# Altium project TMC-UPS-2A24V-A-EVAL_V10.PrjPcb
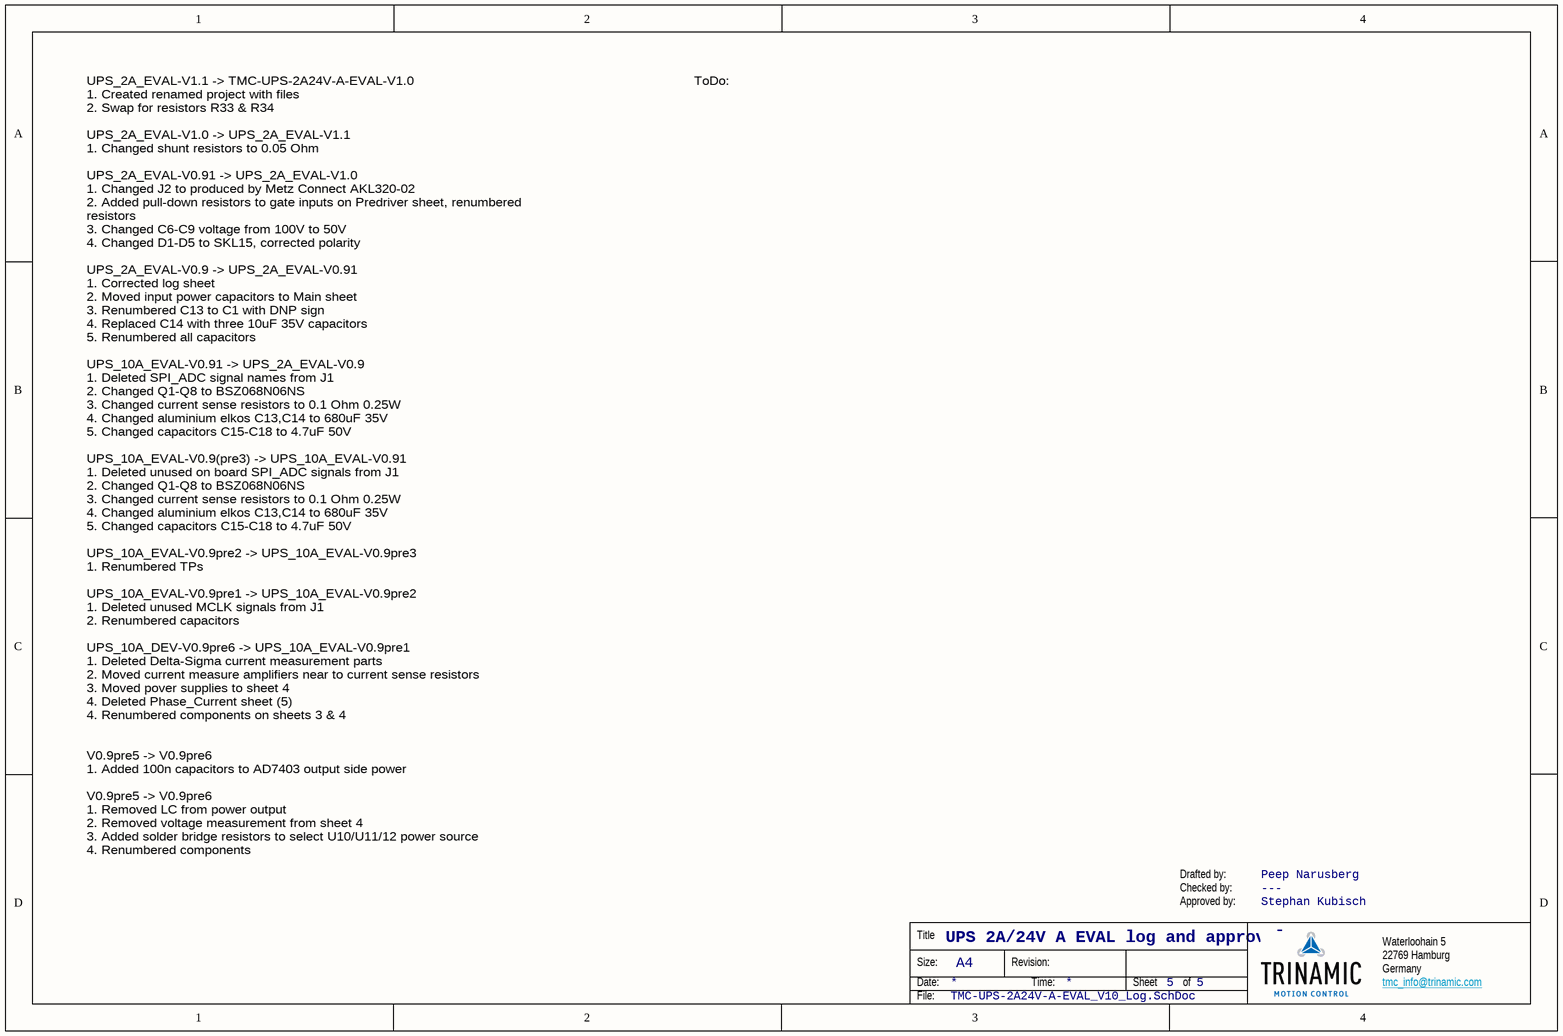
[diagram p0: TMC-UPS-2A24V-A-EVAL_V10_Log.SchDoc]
PName: UPS 2A/24V A EVAL; PRevision: V1.0
5 sheets, 128 parts. Net scope: flat (ports and power ports of the same name join across sheets).
Board file: TMC-UPS-2A24V-A-EVAL_V10.PcbDoc
Sheets:
  TMC-UPS-2A24V-A-EVAL_V10_Log.SchDoc
  TMC-UPS-2A24V-A-EVAL_V10_Main.SchDoc
  TMC-UPS-2A24V-A-EVAL_V10_MOSFETs.SchDoc
  TMC-UPS-2A24V-A-EVAL_V10_Power_Sense.SchDoc
  TMC-UPS-2A24V-A-EVAL_V10_Predriver.SchDoc

## Sheet TMC-UPS-2A24V-A-EVAL_V10_Log.SchDoc: log and approval
size A4; CompanyName: Hedgehog OÜ; Revision: V1.0; SheetNumber: 5; SheetTotal: 5; Author: Peep Narusberg; DrawnBy: Peep Narusberg; Engineer: Peep Narusberg; Organization: Hedgehog OÜ; Address1: Waterloohain 5; Address2: 22769 Hamburg; Address3: Germany; Address4: tmc_info@trinamic.com

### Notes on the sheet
- UPS_2A_EVAL-V1.1 -> TMC-UPS-2A24V-A-EVAL-V1.0
  1. Created renamed project with files
  2. Swap for resistors R33 & R34
  UPS_2A_EVAL-V1.0 -> UPS_2A_EVAL-V1.1
  1. Changed shunt resistors to 0.05 Ohm
  UPS_2A_EVAL-V0.91 -> UPS_2A_EVAL-V1.0
  1. Changed J2 to produced by Metz Connect AKL320-02
  2. Added pull-down resistors to gate inputs on Predriver sheet, renumbered resistors
  3. Changed C6-C9 voltage from 100V to 50V
  4. Changed D1-D5 to SKL15, corrected polarity
  UPS_2A_EVAL-V0.9 -> UPS_2A_EVAL-V0.91
  1. Corrected log sheet
  2. Moved input power capacitors to Main sheet
  3. Renumbered C13 to C1 with DNP sign
  4. Replaced C14 with three 10uF 35V capacitors
  5. Renumbered all capacitors
  UPS_10A_EVAL-V0.91 -> UPS_2A_EVAL-V0.9
  1. Deleted SPI_ADC signal names from J1
  2. Changed Q1-Q8 to BSZ068N06NS
  3. Changed current sense resistors to 0.1 Ohm 0.25W
  4. Changed aluminium elkos C13,C14 to 680uF 35V
  5. Changed capacitors C15-C18 to 4.7uF 50V
  UPS_10A_EVAL-V0.9(pre3) -> UPS_10A_EVAL-V0.91
  1. Deleted unused on board SPI_ADC signals from J1
  2. Changed Q1-Q8 to BSZ068N06NS
  3. Changed current sense resistors to 0.1 Ohm 0.25W
  4. Changed aluminium elkos C13,C14 to 680uF 35V
  5. Changed capacitors C15-C18 to 4.7uF 50V
  UPS_10A_EVAL-V0.9pre2 -> UPS_10A_EVAL-V0.9pre3
  1. Renumbered TPs
  UPS_10A_EVAL-V0.9pre1 -> UPS_10A_EVAL-V0.9pre2
  1. Deleted unused MCLK signals from J1
  2. Renumbered capacitors
  UPS_10A_DEV-V0.9pre6 -> UPS_10A_EVAL-V0.9pre1
  1. Deleted Delta-Sigma current measurement parts
  2. Moved current measure amplifiers near to current sense resistors
  3. Moved pover supplies to sheet 4
  4. Deleted Phase_Current sheet (5)
  4. Renumbered components on sheets 3 & 4
  V0.9pre5 -> V0.9pre6
  1. Added 100n capacitors to AD7403 output side power
  V0.9pre5 -> V0.9pre6
  1. Removed LC from power output
  2. Removed voltage measurement from sheet 4
  3. Added solder bridge resistors to select U10/U11/12 power source
  4. Renumbered components
  V0.9pre4 -> V0.9pre5
  1. Renamed net between J1 pin 9 and U8 pin 7 to MCLK_W
  2. Removed RC-s from power outputs
  3. Removed jumpers from current shunt circuit
  4. Disconnected J1 pin 5 from +5V
  5. Deleted SPI ADC part of circuit
  6. Corrected sheet 5 layout
  7. Corrected phase voltage net names
  8. Renumbered components
  V0.9pre3 -> V0.9pre4
  1. Added D5-D9 zeners
  2. Corrected net name HO_V_X2 for Q5
  3. Corrected SPI SDO signals (swap)
  V0.9pre2  -> V0.9pre3
  1. Added +3.3V source U16
  2. Added missing net names to JP3&4
  3. Checked current sense resistors calculation, changed footprint to 2010[5025 Metric]
  V0.9pre1 -> V0.9pre2
  1. Corrected net and port names
- ToDo:
- Drafted by:
- Checked by:
- Approved by:
- Peep Narusberg
- ---
- Stephan Kubisch

## Sheet TMC-UPS-2A24V-A-EVAL_V10_Main.SchDoc: Main & I/O
size A4; CompanyName: Hedgehog OÜ; Revision: 1; SheetNumber: 1; SheetTotal: 5; DrawnBy: Peep Narusberg; Engineer: Peep Narusberg; Organization: Hedgehog OÜ; Address1: Waterloohain 5; Address2: 22769 Hamburg; Address3: Germany; Address4: tmc_info@trinamic.com
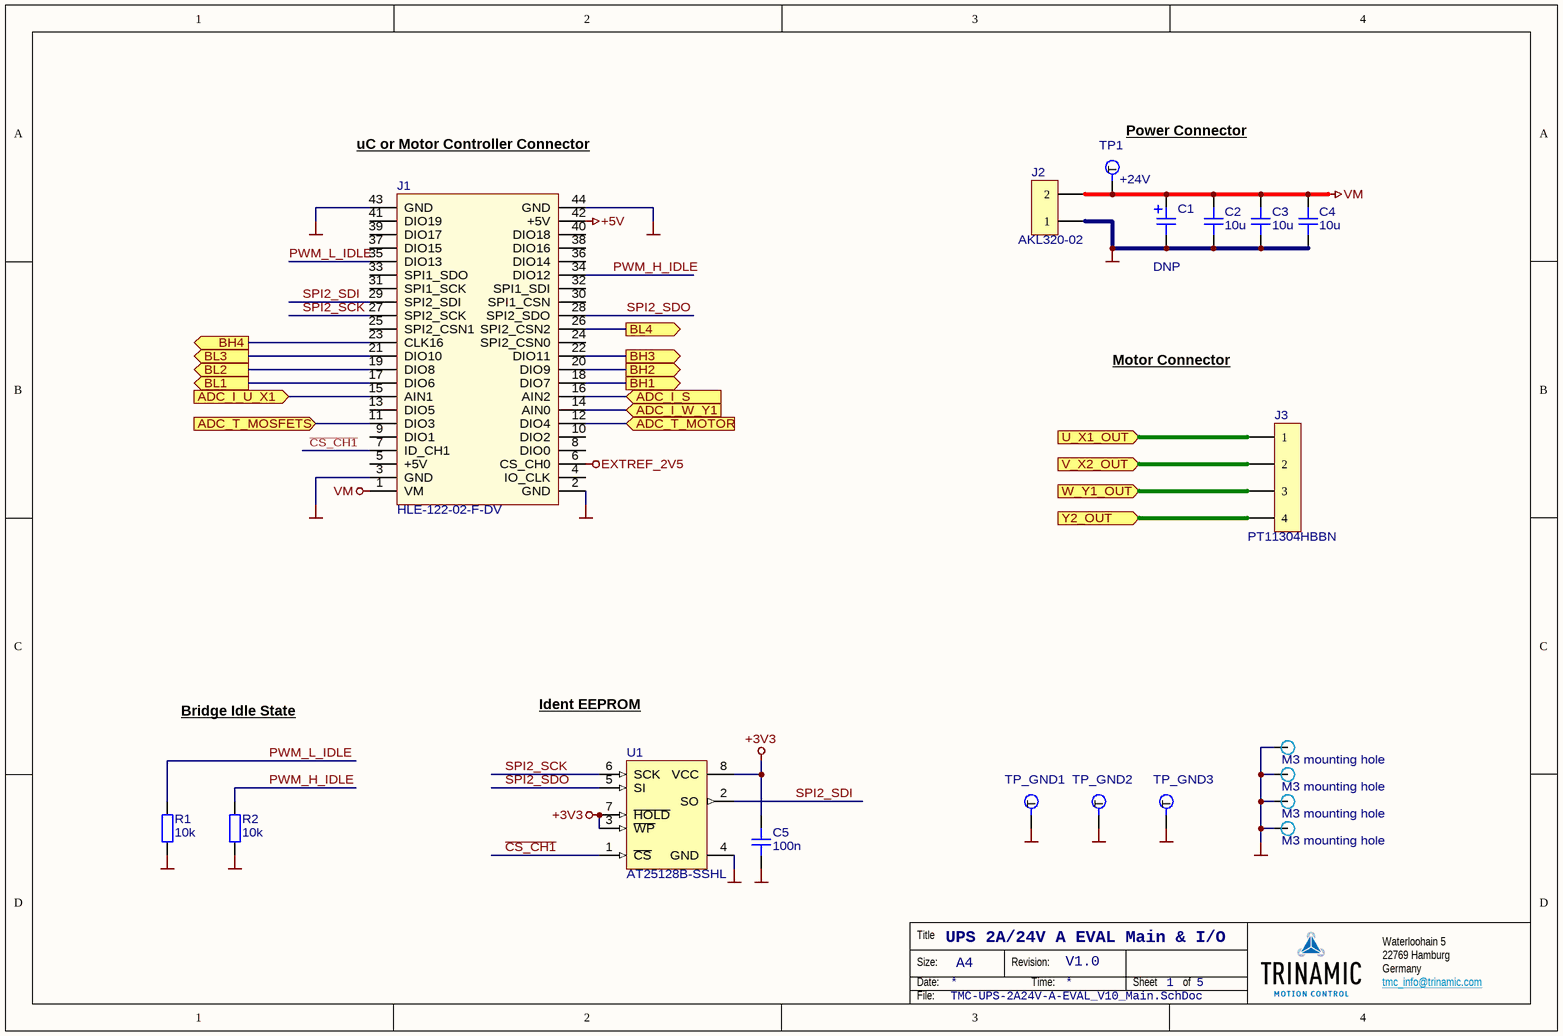
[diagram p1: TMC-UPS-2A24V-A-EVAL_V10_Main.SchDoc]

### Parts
C1  Part Number: DNP  [CAPAE12_5X20]  (hidden comment: CAPP2)
C2  value 10u  [CAPC3216N]  (hidden comment: CAPC)
C3  value 10u  [CAPC3216N]  (hidden comment: CAPC)
C4  value 10u  [CAPC3216N]  (hidden comment: CAPC)
C5  value 100n  [CAPC1608N]  (hidden comment: CAPC)
J1  PTC  [HLE-122-02-F-DV]  (value not drawn)
J2  HDR1x2A  [AKL320-02]  (value not drawn)
J3  HDR1x4A  [PT11304HBBN]  (value not drawn)
MP1  Part Number: M3 mounting hole  [MTG3,2_6,4-VIA]  (hidden comment: MTG)  (no BOM)
MP2  Part Number: M3 mounting hole  [MTG3,2_6,4-VIA]  (hidden comment: MTG)  (no BOM)
MP3  Part Number: M3 mounting hole  [MTG3,2_6,4-VIA]  (hidden comment: MTG)  (no BOM)
MP4  Part Number: M3 mounting hole  [MTG3,2_6,4-VIA]  (hidden comment: MTG)  (no BOM)
R1  value 10k  [RESC1608N]  (hidden comment: RESC)
R2  value 10k  [RESC1608N]  (hidden comment: RESC)
TP1  +24V  [TP100P254]  (no BOM)
TP_GND1  GND  [TP100P254-TH]  (value not drawn)  (no BOM)
TP_GND2  GND  [TP100P254-TH]  (value not drawn)  (no BOM)
TP_GND3  GND  [TP100P254]  (value not drawn)  (no BOM)
U1  Part Number: AT25128B-SSHL  [SOIC127P600X175-8N]

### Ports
ADC_I_S (in), ADC_I_U_X1 (in), ADC_I_W_Y1 (in), ADC_T_MOSFETS (in), ADC_T_MOTOR (in), BH1 (out), BH2 (out), BH3 (out), BH4 (out), BL1 (out), BL2 (out), BL3 (out), BL4 (out), U_X1_OUT (in), V_X2_OUT (in), W_Y1_OUT (in), Y2_OUT (in)

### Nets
+3V3: C5.2 U1.3(~{WP}) U1.7(~{HOLD}) U1.8(VCC)
+5V: J1.42(+5V)
EXTREF_2V5: J1.6(CS_CH0)
GND: C1.1 C2.1 C3.1 C4.1 C5.1 J1.2(GND) J1.3(GND) J1.43(GND) J1.44(GND) J2.1 MP1.1(GND) MP2.1(GND) MP3.1(GND) MP4.1(GND) R1.1 R2.1 TP_GND1.1(T) TP_GND2.1(T) TP_GND3.1(T) U1.4(GND)
VM: C1.2 C2.2 C3.2 C4.2 J1.1(VM) J2.2 TP1.1(T)
~{CS_CH1}: J1.7(ID_CH1) U1.1(~{CS})
PWM_H_IDLE: J1.34(DIO12) R2.2
PWM_L_IDLE: J1.35(DIO13) R1.2
SPI2_SCK: J1.27(SPI2_SCK) U1.6(SCK)
SPI2_SDI: J1.29(SPI2_SDI) U1.2(SO)
SPI2_SDO: J1.28(SPI2_SDO) U1.5(SI)
NetC7_2: J3.2 ; port V_X2_OUT
NetC9_2: J3.4 ; port Y2_OUT
NetC24_2: J1.16(AIN2) ; port ADC_I_S
NetC25_2: J1.11(DIO3) ; port ADC_T_MOSFETS
NetC26_2: J1.12(DIO4) ; port ADC_T_MOTOR
NetC28_2: J1.15(AIN1) ; port ADC_I_U_X1
NetC30_2: J1.14(AIN0) ; port ADC_I_W_Y1
NetJ1_17: J1.17(DIO6) ; port BL1
NetJ1_18: J1.18(DIO7) ; port BH1
NetJ1_19: J1.19(DIO8) ; port BL2
NetJ1_20: J1.20(DIO9) ; port BH2
NetJ1_21: J1.21(DIO10) ; port BL3
NetJ1_22: J1.22(DIO11) ; port BH3
NetJ1_23: J1.23(CLK16) ; port BH4
NetJ1_26: J1.26(SPI2_CSN2) ; port BL4
NetJ3_1: J3.1 ; port U_X1_OUT
NetJ3_3: J3.3 ; port W_Y1_OUT

Not connected (* = marked no-connect by the designer): J1 4(IO_CLK) 5(+5V) 8(DIO0) 9(DIO1) 10(DIO2) 13(DIO5) 24(SPI2_CSN0) 25(SPI2_CSN1) 30(SPI1_CSN) 31(SPI1_SCK) 32(SPI1_SDI) 33(SPI1_SDO) 36(DIO14) 37(DIO15) 38(DIO16) 39(DIO17) 40(DIO18) 41(DIO19)

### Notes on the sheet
- uC or Motor Controller Connector
- Power Connector
- Motor Connector
- Bridge Idle State
- Ident EEPROM

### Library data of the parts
C1 = 50527: Polarized capacitor, pin 1 neg; Id: 50527; Type: CAP
C2-C4 = 20034: Ceramic chip capacitor; Manufacturer: Any; Part Number: 10u, 35V, X5R, 1206 (3216 metric) chip capacitor; Id: 20034; Voltage: 35V
C5 = 20027: Ceramic chip capacitor; Manufacturer: Any; Part Number: 100n, 50V, X5R, 0603 (1608 metric) chip capacitor; Id: 20027; Voltage: 50V
J1 = 50289: Trinamic 44-pin connector; Manufacturer: Samtec; Id: 50289; Value: 44pin
J2 = 50537: 1X2 pin connector; Manufacturer: Metz Connect; Id: 50537; Value: 2 pin
J3 = 50511: 1X4 pin connector; Manufacturer: Metz Connect; Id: 50511; Value: 4 pin, 3.5mm
MP1-MP4 = 50193: Mounting hole; Id: 50193; Value: 3.2x6.4 VIA
R1 R2 = 10028: Chip Resistor; Manufacturer: Any; Part Number: 10k, 1%, 100mW, 0603 (1608 metric) chip resistor; Id: 10028; Power: 100mW; Tolerance: 1%
TP1 TP_GND3 = 50094: Round testpoint; Id: 50094; Value: c160 (P100 probe)
TP_GND1 TP_GND2 = 50149: Round testpoint; Id: 50149; Value: c160h100 (P100 TH)
U1 = 50499: SPI Serial Flash Memory; Manufacturer: Atmel; Id: 50499; Value: 128Kb

## Sheet TMC-UPS-2A24V-A-EVAL_V10_MOSFETs.SchDoc: MOSFETs
size A4; CompanyName: Hedgehog OÜ; Revision: 1; SheetNumber: 3; SheetTotal: 5; DrawnBy: Peep Narusberg; Engineer: Peep Narusberg; Organization: Hedgehog OÜ; Address1: Waterloohain 5; Address2: 22769 Hamburg; Address3: Germany; Address4: tmc_info@trinamic.com
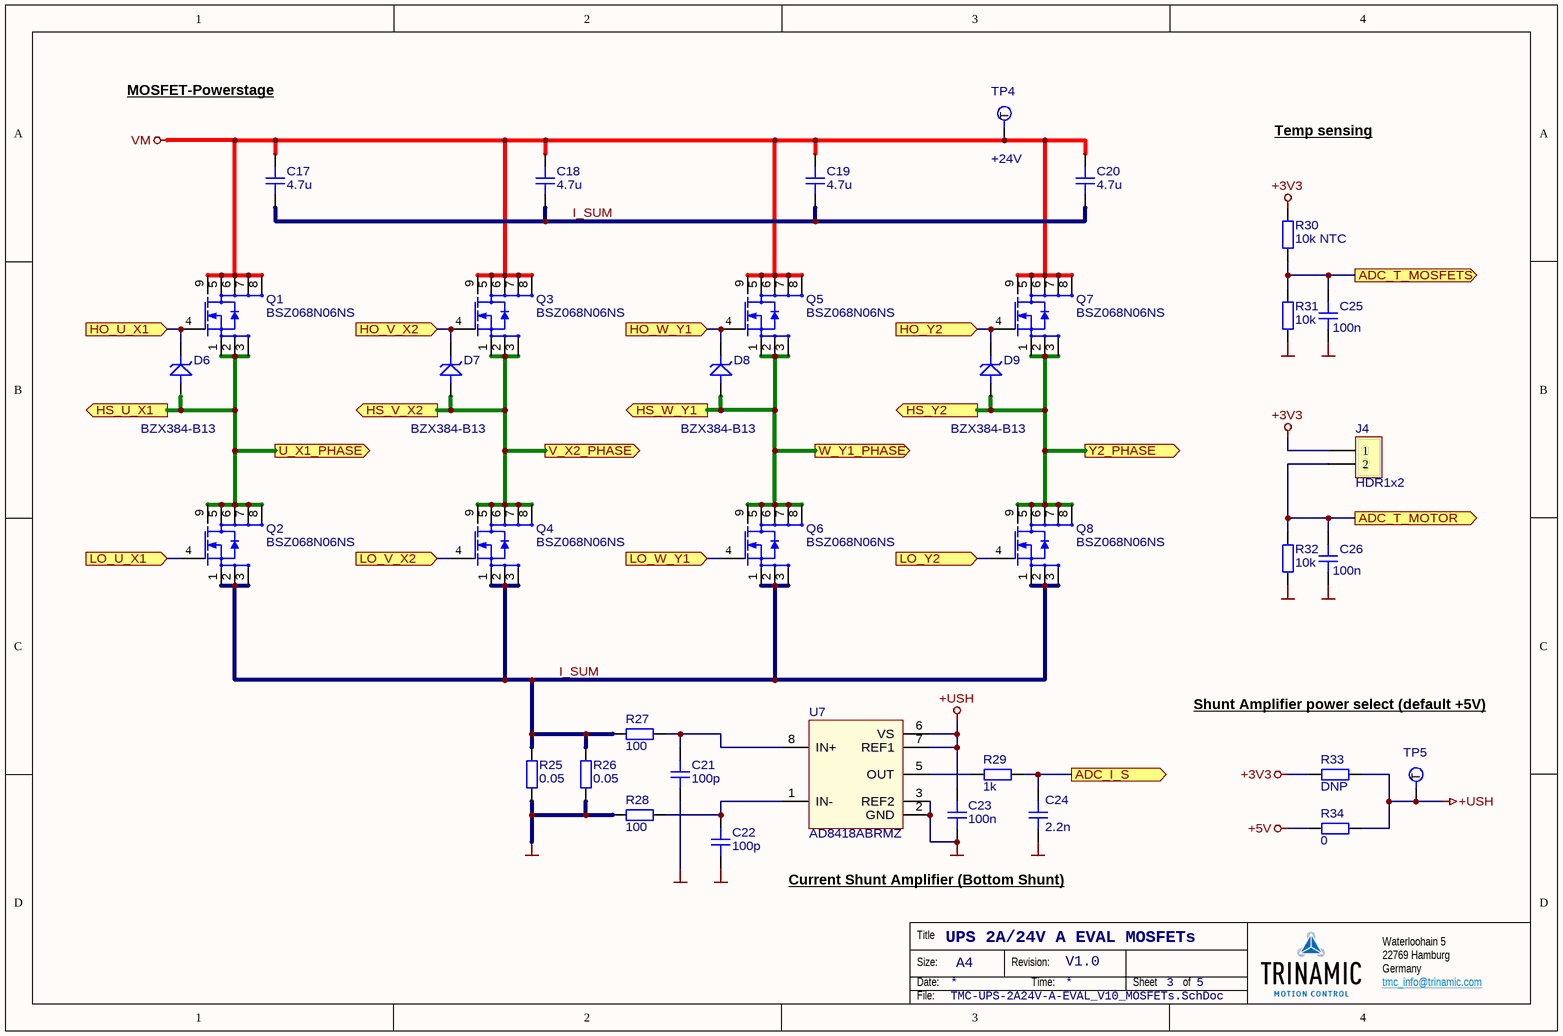
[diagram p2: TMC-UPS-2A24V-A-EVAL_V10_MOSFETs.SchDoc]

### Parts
C17  value 4.7u  [CAPC3216N]  (hidden comment: CAPC)
C18  value 4.7u  [CAPC3216N]  (hidden comment: CAPC)
C19  value 4.7u  [CAPC3216N]  (hidden comment: CAPC)
C20  value 4.7u  [CAPC3216N]  (hidden comment: CAPC)
C21  value 100p  [CAPC1608N]  (hidden comment: CAPC)
C22  value 100p  [CAPC1608N]  (hidden comment: CAPC)
C23  value 100n  [CAPC1608N]  (hidden comment: CAPC)
C24  value 2.2n  [CAPC1608N]
C25  value 100n  [CAPC1608N]  (hidden comment: CAPC)
C26  value 100n  [CAPC1608N]  (hidden comment: CAPC)
D6  Part Number: BZX384-B13  [SOD2512X100N]  (hidden comment: ZENER)
D7  Part Number: BZX384-B13  [SOD2512X100N]  (hidden comment: ZENER)
D8  Part Number: BZX384-B13  [SOD2512X100N]  (hidden comment: ZENER)
D9  Part Number: BZX384-B13  [SOD2512X100N]  (hidden comment: ZENER)
J4  HDR1x2  [HDRP1X2_2_54]
Q1  Part Number: BSZ068N06NS  [DFN65P300X90_HS-9N]  (hidden comment: MOSFET-ENH-N-8A)
Q2  Part Number: BSZ068N06NS  [DFN65P300X90_HS-9N]  (hidden comment: MOSFET-ENH-N-8A)
Q3  Part Number: BSZ068N06NS  [DFN65P300X90_HS-9N]  (hidden comment: MOSFET-ENH-N-8A)
Q4  Part Number: BSZ068N06NS  [DFN65P300X90_HS-9N]  (hidden comment: MOSFET-ENH-N-8A)
Q5  Part Number: BSZ068N06NS  [DFN65P300X90_HS-9N]  (hidden comment: MOSFET-ENH-N-8A)
Q6  Part Number: BSZ068N06NS  [DFN65P300X90_HS-9N]  (hidden comment: MOSFET-ENH-N-8A)
Q7  Part Number: BSZ068N06NS  [DFN65P300X90_HS-9N]  (hidden comment: MOSFET-ENH-N-8A)
Q8  Part Number: BSZ068N06NS  [DFN65P300X90_HS-9N]  (hidden comment: MOSFET-ENH-N-8A)
R25  value 0.05  [RESC2012N]  (hidden comment: RESC)
R26  value 0.05  [RESC2012N]  (hidden comment: RESC)
R27  value 100  [RESC1608N]  (hidden comment: RESC)
R28  value 100  [RESC1608N]  (hidden comment: RESC)
R29  value 1k  [RESC1608N]  (hidden comment: RESC)
R30  value 10k NTC  [RESC1608N]  (hidden comment: RESC)
R31  value 10k  [RESC1608N]  (hidden comment: RESC)
R32  value 10k  [RESC1608N]  (hidden comment: RESC)
R33  value DNP  [RESC1608N]  (hidden comment: RESC)
R34  value 0  [RESC1608N]  (hidden comment: RESC)
TP4  +24V  [TP100P254]  (no BOM)
TP5  +USH  [TP100P254]  (value not drawn)  (no BOM)
U7  Part Number: AD8418ABRMZ  [TSOP65P490X95-8N]  (hidden comment: *)

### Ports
ADC_I_S (out), ADC_T_MOSFETS (out), ADC_T_MOTOR (out), HO_U_X1 (in), HO_V_X2 (in), HO_W_Y1 (in), HO_Y2 (in), HS_U_X1 (out), HS_V_X2 (out), HS_W_Y1 (out), HS_Y2 (out), LO_U_X1 (in), LO_V_X2 (in), LO_W_Y1 (in), LO_Y2 (in), U_X1_PHASE (out), V_X2_PHASE (out), W_Y1_PHASE (out), Y2_PHASE (out)

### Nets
+3V3: J4.1 R30.2 R33.1
+5V: R34.1
+USH: C23.2 R33.2 R34.2 TP5.1(T) U7.6(VS) U7.7(REF1)
GND: C21.1 C22.1 C23.1 C24.1 C25.1 C26.1 R25.1 R26.1 R28.1 R31.1 R32.1 U7.2(GND) U7.3(REF2)
VM: C17.2 C18.2 C19.2 C20.2 Q1.5(D) Q1.6(D) Q1.7(D) Q1.8(D) Q1.9(D) Q3.5(D) Q3.6(D) Q3.7(D) Q3.8(D) Q3.9(D) Q5.5(D) Q5.6(D) Q5.7(D) Q5.8(D) Q5.9(D) Q7.5(D) Q7.6(D) Q7.7(D) Q7.8(D) Q7.9(D) TP4.1(T)
I_SUM: C17.1 C18.1 C19.1 C20.1 Q2.1(S) Q2.2(S) Q2.3(S) Q4.1(S) Q4.2(S) Q4.3(S) Q6.1(S) Q6.2(S) Q6.3(S) Q8.1(S) Q8.2(S) Q8.3(S) R25.2 R26.2 R27.1
NetC6_2: D6.2(A) Q1.1(S) Q1.2(S) Q1.3(S) Q2.5(D) Q2.6(D) Q2.7(D) Q2.8(D) Q2.9(D) ; port HS_U_X1, port U_X1_PHASE
NetC7_2: D7.2(A) Q3.1(S) Q3.2(S) Q3.3(S) Q4.5(D) Q4.6(D) Q4.7(D) Q4.8(D) Q4.9(D) ; port HS_V_X2, port V_X2_PHASE
NetC8_2: D8.2(A) Q5.1(S) Q5.2(S) Q5.3(S) Q6.5(D) Q6.6(D) Q6.7(D) Q6.8(D) Q6.9(D) ; port HS_W_Y1, port W_Y1_PHASE
NetC9_2: D9.2(A) Q7.1(S) Q7.2(S) Q7.3(S) Q8.5(D) Q8.6(D) Q8.7(D) Q8.8(D) Q8.9(D) ; port HS_Y2, port Y2_PHASE
NetC21_2: C21.2 R27.2 U7.8(IN+)
NetC22_2: C22.2 R28.2 U7.1(IN-)
NetC24_2: C24.2 R29.2 ; port ADC_I_S
NetC25_2: C25.2 R30.1 R31.2 ; port ADC_T_MOSFETS
NetC26_2: C26.2 J4.2 R32.2 ; port ADC_T_MOTOR
NetD6_1: D6.1(K) Q1.4(G) ; port HO_U_X1
NetD7_1: D7.1(K) Q3.4(G) ; port HO_V_X2
NetD8_1: D8.1(K) Q5.4(G) ; port HO_W_Y1
NetD9_1: D9.1(K) Q7.4(G) ; port HO_Y2
NetQ2_4: Q2.4(G) ; port LO_U_X1
NetQ4_4: Q4.4(G) ; port LO_V_X2
NetQ6_4: Q6.4(G) ; port LO_W_Y1
NetQ8_4: Q8.4(G) ; port LO_Y2
NetR29_1: R29.1 U7.5(OUT)

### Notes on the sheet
- MOSFET-Powerstage
- Temp sensing
- Shunt Amplifier power select (default +5V)
- Current Shunt Amplifier (Bottom Shunt)

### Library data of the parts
C17-C20 = 20078: Ceramic chip capacitor; Manufacturer: Any; Part Number: 4.7u, 50V, X5R, 1206 (3216 metric) chip capacitor; Id: 20078; Voltage: 50V
C21 C22 = 20083: Ceramic chip capacitor; Manufacturer: Any; Part Number: 100p, 100V, C0G/NP0, 0603 (1608 metric) chip capacitor; Id: 20083; Voltage: 100V
C23 C25 C26 = 20027: as C5 on sheet TMC-UPS-2A24V-A-EVAL_V10_Main
C24 = 20056: Ceramic chip capacitor; Manufacturer: Any; Part Number: 2.2n, 50V, C0G/NP0, 0603 (1608 metric) chip capacitor; Id: 20056; Voltage: 50V
D6-D9 = 50513: Zener, pin1 cathode; Manufacturer: Nexperia; Id: 50513; Type: ZEN; Value: 13V, 0.3W
J4 = 50023: 1X2 pin connector; Part Number: 1x2 2.54mm pin header; Manufacturer: Any; Id: 50023; Value: 2 pin
Q1-Q8 = 50524: N-ch Enh-MOSFET; 5,6,7,8D 4G 1,2.3S; Manufacturer: Infineon; Id: 50524; Type: MOSFETN; Value: 60V 40A
R25 R26 = 10172: Chip Resistor; Manufacturer: Any; Part Number: 0.05, 1%, 250mW, 0805 (2012 metric) chip resistor; Id: 10172; Power: 250mW; Tolerance: 1%
R27 R28 = 10016: Chip Resistor; Manufacturer: Any; Part Number: 100, 1%, 100mW, 0603 (1608 metric) chip resistor; Id: 10016; Power: 100mW; Tolerance: 1%
R29 = 10049: Chip Resistor; Manufacturer: Any; Part Number: 1k, 1%, 100mW, 0603 (1608 metric) chip resistor; Id: 10049; Power: 100mW; Tolerance: 1%
R30 = 40000: Chip Resistor; Manufacturer: Epcos; Part Number: B57330V2103J260; Id: 40000; Power: 180mW; Tolerance: 5%
R31 R32 = 10028: as R1 on sheet TMC-UPS-2A24V-A-EVAL_V10_Main
R33 = 40007: Chip Resistor; Id: 40007
R34 = 10054: Chip Resistor; Manufacturer: Any; Part Number: 0, -, -, 0603 (1608 metric) chip resistor; Id: 10054
TP4 TP5 = 50094: as TP1 on sheet TMC-UPS-2A24V-A-EVAL_V10_Main
U7 = 50496: Bidirectional, Zero Drift, Current Sense Amplifier; Manufacturer: Analog Devices; Id: 50496; Value: CMVR=70V

## Sheet TMC-UPS-2A24V-A-EVAL_V10_Power_Sense.SchDoc: Power Sense
size A4; CompanyName: Hedgehog OÜ; Revision: 1; SheetNumber: 4; SheetTotal: 5; DrawnBy: Peep Narusberg; Engineer: Peep Narusberg; Organization: Hedgehog OÜ; Address1: Waterloohain 5; Address2: 22769 Hamburg; Address3: Germany; Address4: tmc_info@trinamic.com
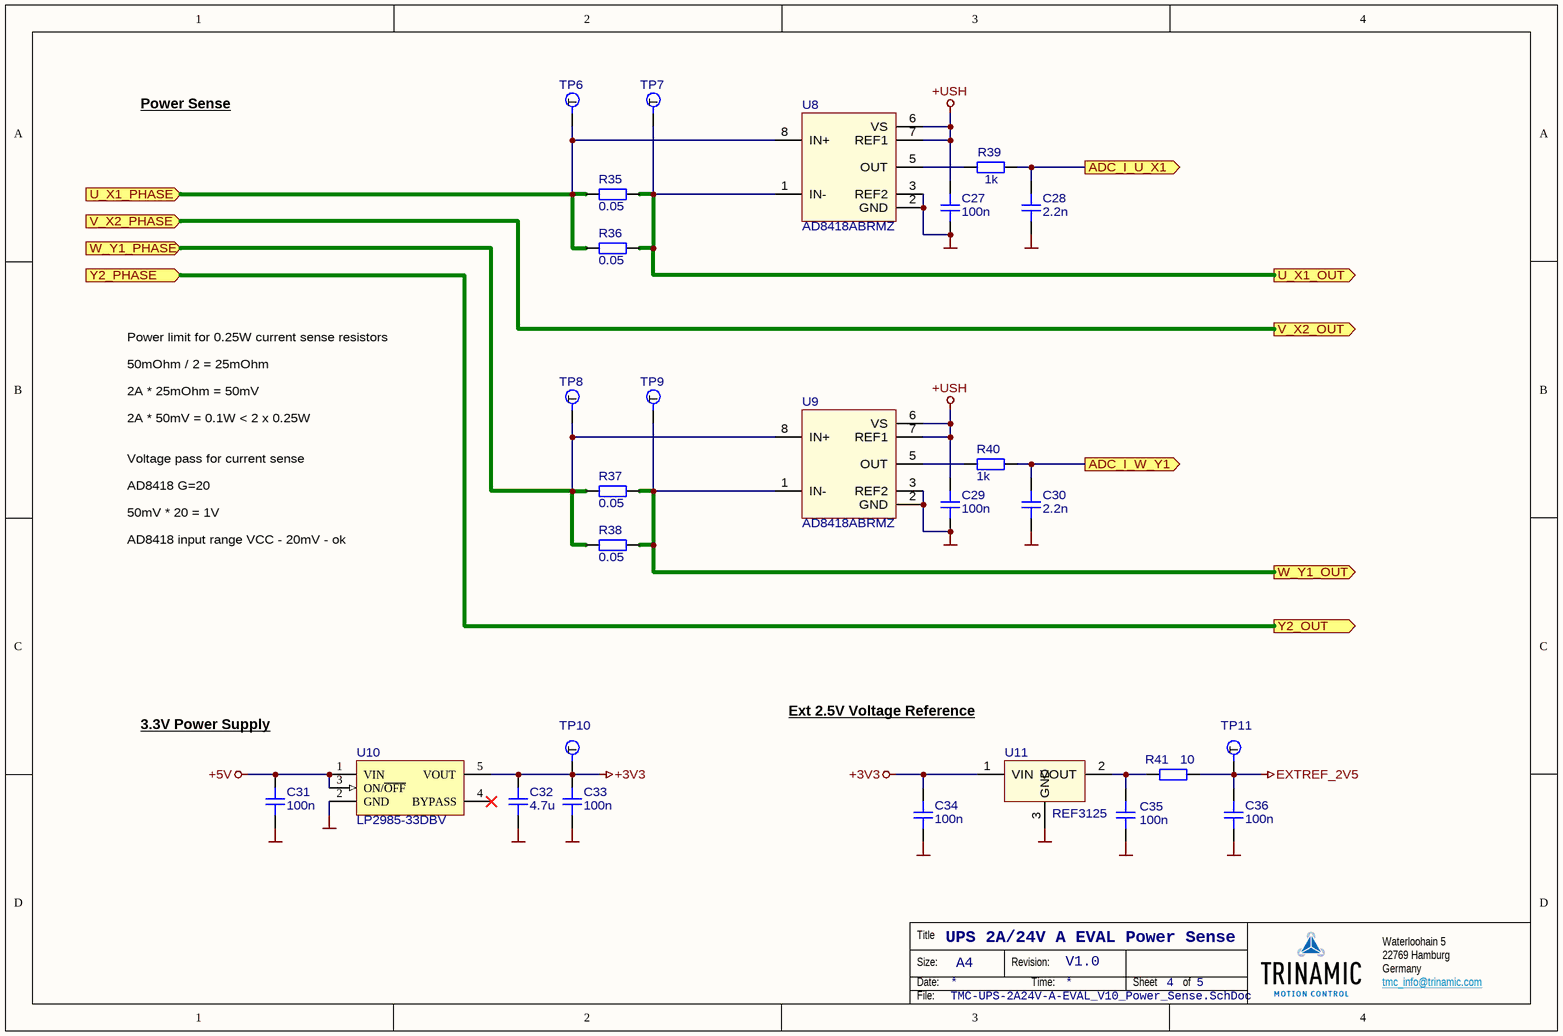
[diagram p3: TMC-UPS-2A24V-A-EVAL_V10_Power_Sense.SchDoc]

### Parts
C27  value 100n  [CAPC1608N]  (hidden comment: CAPC)
C28  value 2.2n  [CAPC1608N]
C29  value 100n  [CAPC1608N]  (hidden comment: CAPC)
C30  value 2.2n  [CAPC1608N]
C31  value 100n  [CAPC1608N]  (hidden comment: CAPC)
C32  value 4.7u  [CAPC1608N]  (hidden comment: CAPC)
C33  value 100n  [CAPC1608N]  (hidden comment: CAPC)
C34  value 100n  [CAPC1608N]  (hidden comment: CAPC)
C35  value 100n  [CAPC1608N]  (hidden comment: CAPC)
C36  value 100n  [CAPC1608N]  (hidden comment: CAPC)
R35  value 0.05  [RESC2012N]  (hidden comment: RESC)
R36  value 0.05  [RESC2012N]  (hidden comment: RESC)
R37  value 0.05  [RESC2012N]  (hidden comment: RESC)
R38  value 0.05  [RESC2012N]  (hidden comment: RESC)
R39  value 1k  [RESC1608N]  (hidden comment: RESC)
R40  value 1k  [RESC1608N]  (hidden comment: RESC)
R41  value 10  [RESC1608N]  (hidden comment: RESC)
TP6  SENSE_X+  [TP100P254]  (value not drawn)  (no BOM)
TP7  SENSE_X-  [TP100P254]  (value not drawn)  (no BOM)
TP8  SENSE_Y+  [TP100P254]  (value not drawn)  (no BOM)
TP9  SENSE_Y-  [TP100P254]  (value not drawn)  (no BOM)
TP10  +3V3  [TP100P254]  (value not drawn)  (no BOM)
TP11  EXTREF 2V5  [TP100P254]  (value not drawn)  (no BOM)
U8  Part Number: AD8418ABRMZ  [TSOP65P490X95-8N]  (hidden comment: *)
U9  Part Number: AD8418ABRMZ  [TSOP65P490X95-8N]  (hidden comment: *)
U10  Part Number: LP2985-33DBV  [SOT95P270X145-5N]
U11  Part Number: REF3125  [SOT95P280X130-3N]  (hidden comment: *)

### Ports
ADC_I_U_X1 (out), ADC_I_W_Y1 (out), U_X1_OUT (out), U_X1_PHASE (in), V_X2_OUT (out), V_X2_PHASE (in), W_Y1_OUT (out), W_Y1_PHASE (in), Y2_OUT (out), Y2_PHASE (in)

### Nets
+3V3: C32.2 C33.2 C34.2 TP10.1(T) U10.5(VOUT) U11.1(VIN)
+5V: C31.2 U10.1(VIN) U10.3(ON/~{OFF})
+USH: C27.1 C29.2 U8.6(VS) U8.7(REF1) U9.6(VS) U9.7(REF1)
EXTREF_2V5: C36.2 R41.2 TP11.1(T)
GND: C27.2 C28.1 C29.1 C30.1 C31.1 C32.1 C33.1 C34.1 C35.1 C36.1 U8.2(GND) U8.3(REF2) U9.2(GND) U9.3(REF2) U10.2(GND) U11.3(GND)
NetC6_2: R35.1 R36.1 TP6.1(T) U8.8(IN+) ; port U_X1_PHASE
NetC7_2: port V_X2_PHASE, port V_X2_OUT
NetC8_2: R37.1 R38.1 TP8.1(T) U9.8(IN+) ; port W_Y1_PHASE
NetC9_2: port Y2_PHASE, port Y2_OUT
NetC28_2: C28.2 R39.2 ; port ADC_I_U_X1
NetC30_2: C30.2 R40.2 ; port ADC_I_W_Y1
NetC35_2: C35.2 R41.1 U11.2(VOUT)
NetJ3_1: R35.2 R36.2 TP7.1(T) U8.1(IN-) ; port U_X1_OUT
NetJ3_3: R37.2 R38.2 TP9.1(T) U9.1(IN-) ; port W_Y1_OUT
NetR39_1: R39.1 U8.5(OUT)
NetR40_1: R40.1 U9.5(OUT)

Not connected (* = marked no-connect by the designer): U10 4(BYPASS)*

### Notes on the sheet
- Power Sense
- Power limit for 0.25W current sense resistors
  50mOhm / 2 = 25mOhm
  2A * 25mOhm = 50mV
  2A * 50mV = 0.1W < 2 x 0.25W
  Voltage pass for current sense
  AD8418 G=20
  50mV * 20 = 1V
  AD8418 input range VCC - 20mV - ok
- Ext 2.5V Voltage Reference
- 3.3V Power Supply

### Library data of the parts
C27 C29 C31 C33-C36 = 20027: as C5 on sheet TMC-UPS-2A24V-A-EVAL_V10_Main
C28 C30 = 20056: as C24 on sheet TMC-UPS-2A24V-A-EVAL_V10_MOSFETs
C32 = 20084: Ceramic chip capacitor; Manufacturer: Any; Part Number: 4.7u, 10V, X5R, 0603 (1608 metric) chip capacitor; Id: 20084; Voltage: 10V
R35-R38 = 10172: as R25 on sheet TMC-UPS-2A24V-A-EVAL_V10_MOSFETs
R39 R40 = 10049: as R29 on sheet TMC-UPS-2A24V-A-EVAL_V10_MOSFETs
R41 = 10002: Chip Resistor; Manufacturer: Any; Part Number: 10, 1%, 100mW, 0603 (1608 metric) chip resistor; Id: 10002; Power: 100mW; Tolerance: 1%
TP6-TP11 = 50094: as TP1 on sheet TMC-UPS-2A24V-A-EVAL_V10_Main
U8 U9 = 50496: as U7 on sheet TMC-UPS-2A24V-A-EVAL_V10_MOSFETs
U10 = 50426: 150-mA Low-noise LDO; Manufacturer: Texas Instruments; Id: 50426; Value: 150mA 3.3V
U11 = 50316: Series voltage reference; Manufacturer: Texas Instruments; Id: 50316; Value: 2.5V

## Sheet TMC-UPS-2A24V-A-EVAL_V10_Predriver.SchDoc: Predrivers
size A4; CompanyName: Hedgehog OÜ; Revision: 1; SheetNumber: 2; SheetTotal: 6; DrawnBy: Peep Narusberg; Engineer: Peep Narusberg; Organization: Hedgehog OÜ; Address1: Waterloohain 5; Address2: 22769 Hamburg; Address3: Germany; Address4: tmc_info@trinamic.com
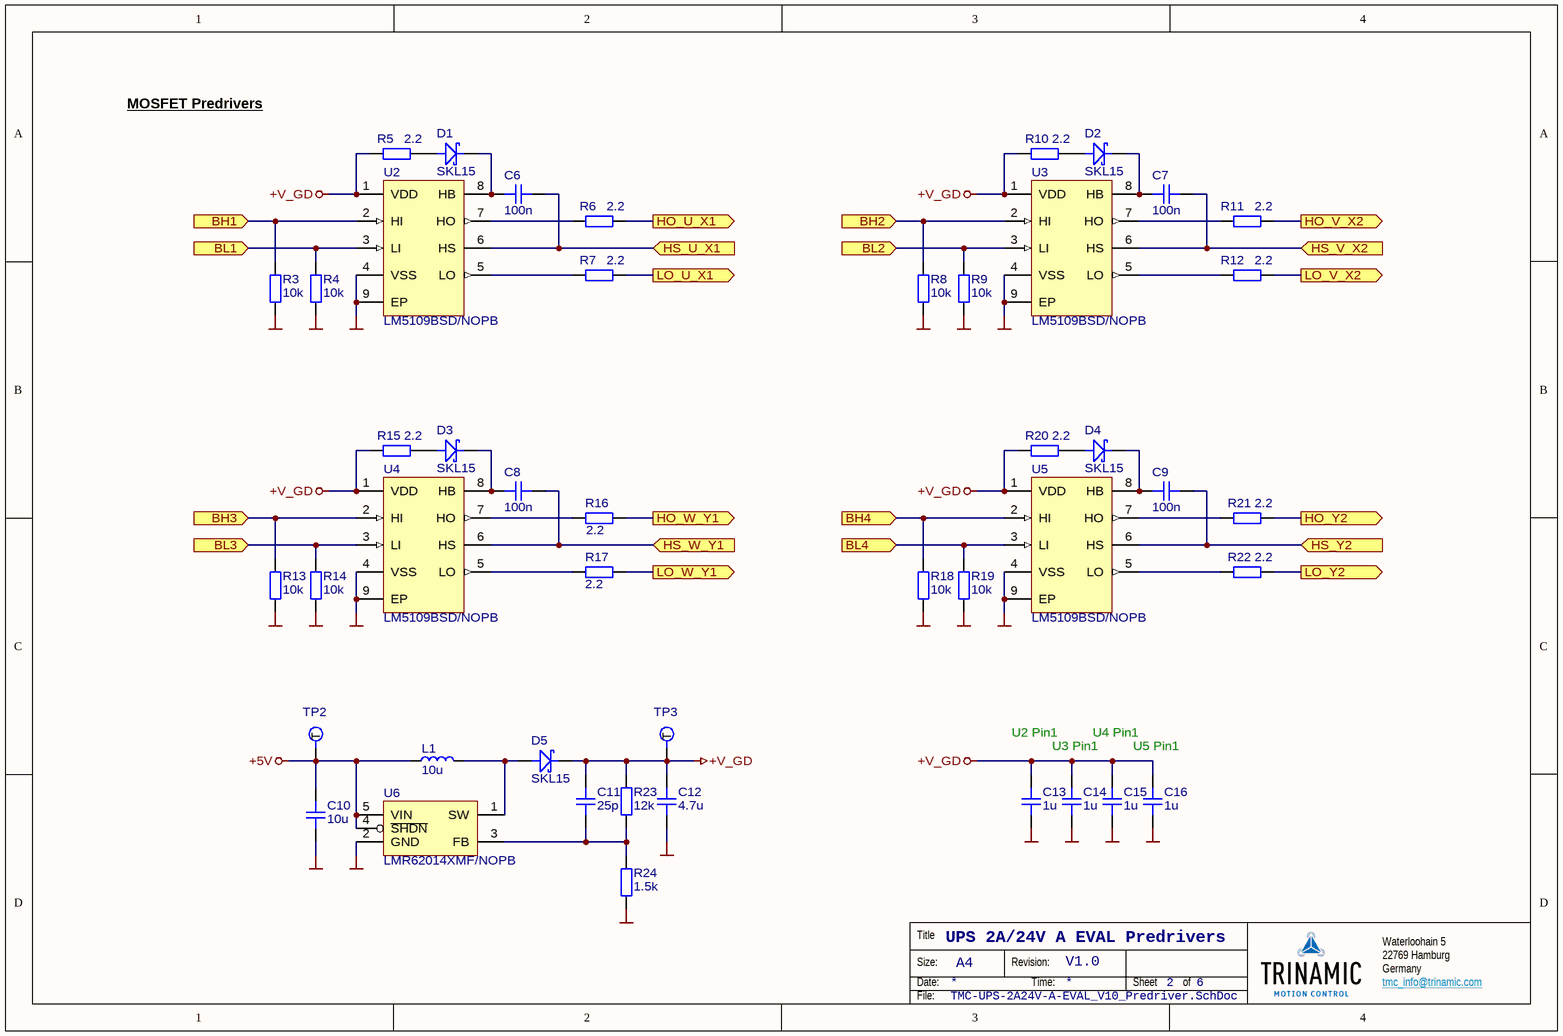
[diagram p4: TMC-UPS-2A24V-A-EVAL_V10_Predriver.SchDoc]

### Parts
C6  value 100n  [CAPC1608N]  (hidden comment: CAPC)
C7  value 100n  [CAPC1608N]  (hidden comment: CAPC)
C8  value 100n  [CAPC1608N]  (hidden comment: CAPC)
C9  value 100n  [CAPC1608N]  (hidden comment: CAPC)
C10  value 10u  [CAPC1608N]  (hidden comment: CAPC)
C11  value 25p  [CAPC1608N]  (hidden comment: CAPC)
C12  value 4.7u  [CAPC1608N]  (hidden comment: CAPC)
C13  value 1u  [CAPC1608N]  (hidden comment: CAPC)
C14  value 1u  [CAPC1608N]  (hidden comment: CAPC)
C15  value 1u  [CAPC1608N]  (hidden comment: CAPC)
C16  value 1u  [CAPC1608N]  (hidden comment: CAPC)
D1  Part Number: SKL15  [SODFL370X140-2N]  (hidden comment: DIO-SCHOTTKY)
D2  Part Number: SKL15  [SODFL370X140-2N]  (hidden comment: DIO-SCHOTTKY)
D3  Part Number: SKL15  [SODFL370X140-2N]  (hidden comment: DIO-SCHOTTKY)
D4  Part Number: SKL15  [SODFL370X140-2N]  (hidden comment: DIO-SCHOTTKY)
D5  Part Number: SKL15  [SODFL370X140-2N]  (hidden comment: DIO-SCHOTTKY)
L1  value 10u  [744031100]  (hidden comment: INDM)
R3  value 10k  [RESC1608N]  (hidden comment: RESC)
R4  value 10k  [RESC1608N]  (hidden comment: RESC)
R5  value 2.2  [RESC1608N]
R6  value 2.2  [RESC1608N]
R7  value 2.2  [RESC1608N]
R8  value 10k  [RESC1608N]  (hidden comment: RESC)
R9  value 10k  [RESC1608N]  (hidden comment: RESC)
R10  value 2.2  [RESC1608N]
R11  value 2.2  [RESC1608N]
R12  value 2.2  [RESC1608N]
R13  value 10k  [RESC1608N]  (hidden comment: RESC)
R14  value 10k  [RESC1608N]  (hidden comment: RESC)
R15  value 2.2  [RESC1608N]
R16  value 2.2  [RESC1608N]
R17  value 2.2  [RESC1608N]
R18  value 10k  [RESC1608N]  (hidden comment: RESC)
R19  value 10k  [RESC1608N]  (hidden comment: RESC)
R20  value 2.2  [RESC1608N]
R21  value 2.2  [RESC1608N]
R22  value 2.2  [RESC1608N]
R23  value 12k  [RESC1608N]  (hidden comment: RESC)
R24  value 1.5k  [RESC1608N]  (hidden comment: RESC)
TP2  +5V  [TP100P254]  (value not drawn)  (no BOM)
TP3  +V_GD  [TP100P254]  (value not drawn)  (no BOM)
U2  Part Number: LM5109BSD/NOPB  [PSON80P400X80_HS-9N]
U3  Part Number: LM5109BSD/NOPB  [PSON80P400X80_HS-9N]
U4  Part Number: LM5109BSD/NOPB  [PSON80P400X80_HS-9N]
U5  Part Number: LM5109BSD/NOPB  [PSON80P400X80_HS-9N]
U6  Part Number: LMR62014XMF/NOPB  [SOT95P280X145-5N]  (hidden comment: LMR62014)

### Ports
BH1 (in), BH2 (in), BH3 (in), BH4 (in), BL1 (in), BL2 (in), BL3 (in), BL4 (in), HO_U_X1 (out), HO_V_X2 (out), HO_W_Y1 (out), HO_Y2 (out), HS_U_X1 (in), HS_V_X2 (in), HS_W_Y1 (in), HS_Y2 (in), LO_U_X1 (out), LO_V_X2 (out), LO_W_Y1 (out), LO_Y2 (out)

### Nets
+5V: C10.2 L1.1 TP2.1(T) U6.4(~{SHDN}) U6.5(VIN)
+V_GD: C11.2 C12.2 C13.2 C14.2 C15.2 C16.2 D5.1 R5.1 R10.1 R15.1 R20.1 R23.2 TP3.1(T) U2.1(VDD) U3.1(VDD) U4.1(VDD) U5.1(VDD)
GND: C10.1 C12.1 C13.1 C14.1 C15.1 C16.1 R3.1 R4.1 R8.1 R9.1 R13.1 R14.1 R18.1 R19.1 R24.1 U2.4(VSS) U2.9(EP) U3.4(VSS) U3.9(EP) U4.4(VSS) U4.9(EP) U5.4(VSS) U5.9(EP) U6.2(GND)
NetC6_1: C6.1 D1.1 U2.8(HB)
NetC6_2: C6.2 U2.6(HS) ; port HS_U_X1
NetC7_1: C7.1 D2.1 U3.8(HB)
NetC7_2: C7.2 U3.6(HS) ; port HS_V_X2
NetC8_1: C8.1 D3.1 U4.8(HB)
NetC8_2: C8.2 U4.6(HS) ; port HS_W_Y1
NetC9_1: C9.1 D4.1 U5.8(HB)
NetC9_2: C9.2 U5.6(HS) ; port HS_Y2
NetC11_1: C11.1 R23.1 R24.2 U6.3(FB)
NetD1_2: D1.2 R5.2
NetD2_2: D2.2 R10.2
NetD3_2: D3.2 R15.2
NetD4_2: D4.2 R20.2
NetD5_2: D5.2 L1.2 U6.1(SW)
NetD6_1: R6.2 ; port HO_U_X1
NetD7_1: R11.2 ; port HO_V_X2
NetD8_1: R16.2 ; port HO_W_Y1
NetD9_1: R21.2 ; port HO_Y2
NetJ1_17: R4.2 U2.3(LI) ; port BL1
NetJ1_18: R3.2 U2.2(HI) ; port BH1
NetJ1_19: R9.2 U3.3(LI) ; port BL2
NetJ1_20: R8.2 U3.2(HI) ; port BH2
NetJ1_21: R14.2 U4.3(LI) ; port BL3
NetJ1_22: R13.2 U4.2(HI) ; port BH3
NetJ1_23: R18.2 U5.2(HI) ; port BH4
NetJ1_26: R19.2 U5.3(LI) ; port BL4
NetQ2_4: R7.2 ; port LO_U_X1
NetQ4_4: R12.2 ; port LO_V_X2
NetQ6_4: R17.2 ; port LO_W_Y1
NetQ8_4: R22.2 ; port LO_Y2
NetR6_1: R6.1 U2.7(HO)
NetR7_1: R7.1 U2.5(LO)
NetR11_1: R11.1 U3.7(HO)
NetR12_1: R12.1 U3.5(LO)
NetR16_1: R16.1 U4.7(HO)
NetR17_1: R17.1 U4.5(LO)
NetR21_1: R21.1 U5.7(HO)
NetR22_1: R22.1 U5.5(LO)

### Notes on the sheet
- MOSFET Predrivers
- U2 Pin1
- U3 Pin1
- U4 Pin1
- U5 Pin1

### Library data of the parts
C6-C9 = 20027: as C5 on sheet TMC-UPS-2A24V-A-EVAL_V10_Main
C10 = 20111: Ceramic chip capacitor; Manufacturer: Any; Part Number: 10u, 10V, X5R, 0603 (1608 metric) chip capacitor; Id: 20111; Voltage: 10V
C11 = 20112: Ceramic chip capacitor; Manufacturer: Any; Part Number: 25p, 50V, C0G/NP0, 0603 (1608 metric) chip capacitor; Id: 20112; Voltage: 50V
C12 = 20113: Ceramic chip capacitor; Manufacturer: Any; Part Number: 4.7u, 25V, X5R, 0603 (1608 metric) chip capacitor; Id: 20113; Voltage: 25V
C13-C16 = 20077: Ceramic chip capacitor; Manufacturer: Any; Part Number: 1u, 25V, X5R, 0603 (1608 metric) chip capacitor; Id: 20077; Voltage: 25V
D1-D5 = 50567: Schottky Diode, pin1 cathode; Manufacturer: Diotec  Semiconductor; Id: 50567; Value: 1A, 50V
L1 = 60031: Molded inductor; Manufacturer: Wuerth; Id: 60031; Tolerance: 30; Current: 740m
R3 R4 R8 R9 R13 R14 R18 R19 = 10028: as R1 on sheet TMC-UPS-2A24V-A-EVAL_V10_Main
R5-R7 R10-R12 R15-R17 R20-R22 = 10041: Chip Resistor; Manufacturer: Any; Part Number: 2.2, 1%, 100mW, 0603 (1608 metric) chip resistor; Id: 10041; Power: 100mW; Tolerance: 1%
R23 = 10078: Chip Resistor; Manufacturer: Any; Part Number: 12k, 1%, 100mW, 0603 (1608 metric) chip resistor; Id: 10078; Power: 100mW; Tolerance: 1%
R24 = 10152: Chip Resistor; Manufacturer: Any; Part Number: 1.5k, 1%, 100mW, 0603 (1608 metric) chip resistor; Id: 10152; Power: 100mW; Tolerance: 1%
TP2 TP3 = 50094: as TP1 on sheet TMC-UPS-2A24V-A-EVAL_V10_Main
U2-U5 = 50490: High Voltage 1A Peak Half Bridge Gate Driver; Manufacturer: Texas Instruments; Id: 50490; Value: 108V 1A
U6 = 50495: LMR62014 SIMPLE SWITCHER® 20Vout, 1.4A Step-Up Voltage Regulator in SOT-23; Manufacturer: Texas Instruments; Id: 50495

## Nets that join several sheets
+3V3: TMC-UPS-2A24V-A-EVAL_V10_Main (C5.2 U1.3 U1.7 U1.8), TMC-UPS-2A24V-A-EVAL_V10_MOSFETs (J4.1 R30.2 R33.1), TMC-UPS-2A24V-A-EVAL_V10_Power_Sense (6 pins)
+5V: TMC-UPS-2A24V-A-EVAL_V10_Main (J1.42), TMC-UPS-2A24V-A-EVAL_V10_MOSFETs (R34.1), TMC-UPS-2A24V-A-EVAL_V10_Power_Sense (C31.2 U10.1 U10.3), TMC-UPS-2A24V-A-EVAL_V10_Predriver (5 pins)
+USH: TMC-UPS-2A24V-A-EVAL_V10_MOSFETs (6 pins), TMC-UPS-2A24V-A-EVAL_V10_Power_Sense (6 pins)
EXTREF_2V5: TMC-UPS-2A24V-A-EVAL_V10_Main (J1.6), TMC-UPS-2A24V-A-EVAL_V10_Power_Sense (C36.2 R41.2 TP11.1)
GND: TMC-UPS-2A24V-A-EVAL_V10_Main (20 pins), TMC-UPS-2A24V-A-EVAL_V10_MOSFETs (13 pins), TMC-UPS-2A24V-A-EVAL_V10_Power_Sense (16 pins), TMC-UPS-2A24V-A-EVAL_V10_Predriver (24 pins)
VM: TMC-UPS-2A24V-A-EVAL_V10_Main (7 pins), TMC-UPS-2A24V-A-EVAL_V10_MOSFETs (25 pins)
NetC6_2: TMC-UPS-2A24V-A-EVAL_V10_MOSFETs (9 pins), TMC-UPS-2A24V-A-EVAL_V10_Power_Sense (R35.1 R36.1 TP6.1 U8.8), TMC-UPS-2A24V-A-EVAL_V10_Predriver (C6.2 U2.6)
NetC7_2: TMC-UPS-2A24V-A-EVAL_V10_Main (J3.2), TMC-UPS-2A24V-A-EVAL_V10_MOSFETs (9 pins), TMC-UPS-2A24V-A-EVAL_V10_Predriver (C7.2 U3.6)
NetC8_2: TMC-UPS-2A24V-A-EVAL_V10_MOSFETs (9 pins), TMC-UPS-2A24V-A-EVAL_V10_Power_Sense (R37.1 R38.1 TP8.1 U9.8), TMC-UPS-2A24V-A-EVAL_V10_Predriver (C8.2 U4.6)
NetC9_2: TMC-UPS-2A24V-A-EVAL_V10_Main (J3.4), TMC-UPS-2A24V-A-EVAL_V10_MOSFETs (9 pins), TMC-UPS-2A24V-A-EVAL_V10_Predriver (C9.2 U5.6)
NetC24_2: TMC-UPS-2A24V-A-EVAL_V10_Main (J1.16), TMC-UPS-2A24V-A-EVAL_V10_MOSFETs (C24.2 R29.2)
NetC25_2: TMC-UPS-2A24V-A-EVAL_V10_Main (J1.11), TMC-UPS-2A24V-A-EVAL_V10_MOSFETs (C25.2 R30.1 R31.2)
NetC26_2: TMC-UPS-2A24V-A-EVAL_V10_Main (J1.12), TMC-UPS-2A24V-A-EVAL_V10_MOSFETs (C26.2 J4.2 R32.2)
NetC28_2: TMC-UPS-2A24V-A-EVAL_V10_Main (J1.15), TMC-UPS-2A24V-A-EVAL_V10_Power_Sense (C28.2 R39.2)
NetC30_2: TMC-UPS-2A24V-A-EVAL_V10_Main (J1.14), TMC-UPS-2A24V-A-EVAL_V10_Power_Sense (C30.2 R40.2)
NetD6_1: TMC-UPS-2A24V-A-EVAL_V10_MOSFETs (D6.1 Q1.4), TMC-UPS-2A24V-A-EVAL_V10_Predriver (R6.2)
NetD7_1: TMC-UPS-2A24V-A-EVAL_V10_MOSFETs (D7.1 Q3.4), TMC-UPS-2A24V-A-EVAL_V10_Predriver (R11.2)
NetD8_1: TMC-UPS-2A24V-A-EVAL_V10_MOSFETs (D8.1 Q5.4), TMC-UPS-2A24V-A-EVAL_V10_Predriver (R16.2)
NetD9_1: TMC-UPS-2A24V-A-EVAL_V10_MOSFETs (D9.1 Q7.4), TMC-UPS-2A24V-A-EVAL_V10_Predriver (R21.2)
NetJ1_17: TMC-UPS-2A24V-A-EVAL_V10_Main (J1.17), TMC-UPS-2A24V-A-EVAL_V10_Predriver (R4.2 U2.3)
NetJ1_18: TMC-UPS-2A24V-A-EVAL_V10_Main (J1.18), TMC-UPS-2A24V-A-EVAL_V10_Predriver (R3.2 U2.2)
NetJ1_19: TMC-UPS-2A24V-A-EVAL_V10_Main (J1.19), TMC-UPS-2A24V-A-EVAL_V10_Predriver (R9.2 U3.3)
NetJ1_20: TMC-UPS-2A24V-A-EVAL_V10_Main (J1.20), TMC-UPS-2A24V-A-EVAL_V10_Predriver (R8.2 U3.2)
NetJ1_21: TMC-UPS-2A24V-A-EVAL_V10_Main (J1.21), TMC-UPS-2A24V-A-EVAL_V10_Predriver (R14.2 U4.3)
NetJ1_22: TMC-UPS-2A24V-A-EVAL_V10_Main (J1.22), TMC-UPS-2A24V-A-EVAL_V10_Predriver (R13.2 U4.2)
NetJ1_23: TMC-UPS-2A24V-A-EVAL_V10_Main (J1.23), TMC-UPS-2A24V-A-EVAL_V10_Predriver (R18.2 U5.2)
NetJ1_26: TMC-UPS-2A24V-A-EVAL_V10_Main (J1.26), TMC-UPS-2A24V-A-EVAL_V10_Predriver (R19.2 U5.3)
NetJ3_1: TMC-UPS-2A24V-A-EVAL_V10_Main (J3.1), TMC-UPS-2A24V-A-EVAL_V10_Power_Sense (R35.2 R36.2 TP7.1 U8.1)
NetJ3_3: TMC-UPS-2A24V-A-EVAL_V10_Main (J3.3), TMC-UPS-2A24V-A-EVAL_V10_Power_Sense (R37.2 R38.2 TP9.1 U9.1)
NetQ2_4: TMC-UPS-2A24V-A-EVAL_V10_MOSFETs (Q2.4), TMC-UPS-2A24V-A-EVAL_V10_Predriver (R7.2)
NetQ4_4: TMC-UPS-2A24V-A-EVAL_V10_MOSFETs (Q4.4), TMC-UPS-2A24V-A-EVAL_V10_Predriver (R12.2)
NetQ6_4: TMC-UPS-2A24V-A-EVAL_V10_MOSFETs (Q6.4), TMC-UPS-2A24V-A-EVAL_V10_Predriver (R17.2)
NetQ8_4: TMC-UPS-2A24V-A-EVAL_V10_MOSFETs (Q8.4), TMC-UPS-2A24V-A-EVAL_V10_Predriver (R22.2)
